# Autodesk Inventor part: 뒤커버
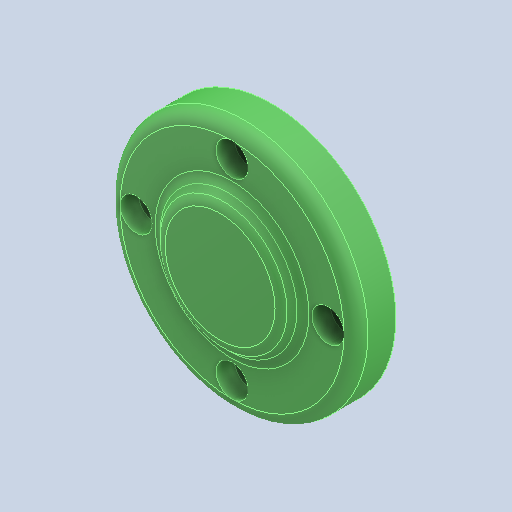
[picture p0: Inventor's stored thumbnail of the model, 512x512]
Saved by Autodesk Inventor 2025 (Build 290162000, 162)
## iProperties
Created: 2024-07
Part Number: 뒤커버
Material: 알루미늄 6061
Document SubType Name: Modeling
Designer: samsung
Density: 2.71 g/cm^3
Appearance: 기본값
Author: jhkim
Sending System: Autodesk Inventor 2025
Preprocessor: ST-DEVELOPER v20
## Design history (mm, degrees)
feature "솔리드1"
node "솔리드2"
